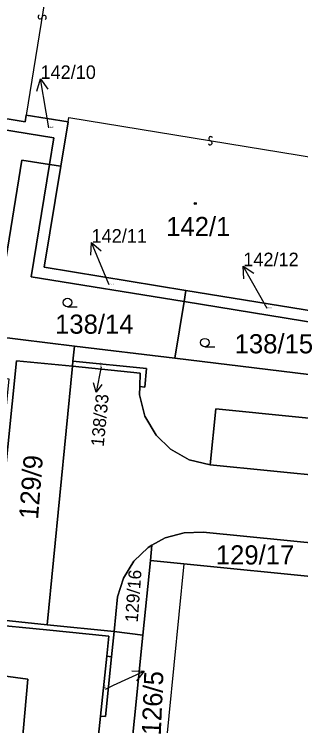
# Model space of a CAD drawing. Extents: x -598233 to -596890, y -1157848 to -1156431.
# Drawn here: x -597952.1 to -597926.7, y -1156881.8 to -1156818.7 of the extents above; entities that cross this region are included whole.
import ezdxf

# ---------------------------------------------------------------- set-up
doc = ezdxf.new("R2010")
doc.units = 0
for name, color, linetype in [('Level 1', 7, 'Continuous'), ('Level 13', 7, 'Continuous'), ('Level 3', 7, 'Continuous'), ('Level 4', 7, 'Continuous'), ('Level 5', 7, 'Continuous'), ('Level 57', 7, 'Continuous'), ('Level 60', 7, 'Continuous')]:
    doc.layers.add(name, color=color, linetype=linetype)

msp = doc.modelspace()

# ---------------------------------------------------------------- linework, layer by layer
at = {"layer": 'Level 1'}
for points in [[(-597951.07, -1156827.62), (-597951.16, -1156828.21), (-597960.5, -1156826.69)], [(-597947.37, -1156828.22), (-597951.07, -1156827.62)], [(-597960.66, -1156827.68), (-597948.63, -1156829.64), (-597949.01, -1156832.01)], [(-597948.02, -1156832.17), (-597947.37, -1156828.22)], [(-597949.01, -1156832.01), (-597951.45, -1156831.62), (-597954, -1156847.25)], [(-597949.01, -1156832.01), (-597950.63, -1156841.96), (-597937.08, -1156844.16)], [(-597949.01, -1156832.01), (-597948.02, -1156832.17)], [(-597948.02, -1156832.17), (-597949.48, -1156841.13), (-597936.92, -1156843.18)], [(-597922.25, -1156832.31), (-597924.36, -1156845.22), (-597936.92, -1156843.18)], [(-597937.08, -1156844.16), (-597923.53, -1156846.37), (-597921.43, -1156833.46), (-597918.2, -1156833.98)], [(-597937.9, -1156849.2), (-597920.2, -1156851.34), (-597918.2, -1156833.98)], [(-597937.08, -1156844.16), (-597936.92, -1156843.18)], [(-597937.08, -1156844.16), (-597937.9, -1156849.2)], [(-597946.8, -1156848.12), (-597954, -1156847.25)], [(-597946.8, -1156848.12), (-597946.93, -1156849.44)], [(-597937.9, -1156849.2), (-597946.8, -1156848.12)], [(-597946.98, -1156849.91), (-597951.92, -1156849.41), (-597954.27, -1156872.32), (-597949.22, -1156872.83)], [(-597946.98, -1156849.91), (-597946.93, -1156849.44)], [(-597946.93, -1156849.44), (-597940.41, -1156850.11), (-597940.57, -1156851.75), (-597941.01, -1156851.71)], [(-597949.22, -1156872.83), (-597946.98, -1156849.91)], [(-597941.01, -1156851.71), (-597940.97, -1156850.51), (-597946.98, -1156849.91)], [(-597941.01, -1156851.71), (-597941.03, -1156852.43), (-597940.55, -1156854.34), (-597939.55, -1156856.03), (-597938.3, -1156857.26), (-597936.63, -1156858.21), (-597934.76, -1156858.66)], [(-597897.36, -1156862.39), (-597896.91, -1156857.43), (-597934.27, -1156853.68), (-597934.76, -1156858.66)], [(-597934.76, -1156858.66), (-597897.36, -1156862.39)], [(-597939.93, -1156865.79), (-597938.76, -1156865.13), (-597937.07, -1156864.67), (-597935.39, -1156864.63), (-597924.39, -1156865.73)], [(-597939.93, -1156865.79), (-597940.28, -1156865.99), (-597941.54, -1156867.2), (-597942.46, -1156868.69), (-597942.98, -1156870.36), (-597943.29, -1156873.42)], [(-597939.93, -1156865.79), (-597940.07, -1156867.14)], [(-597940.73, -1156873.76), (-597940.07, -1156867.14)], [(-597940.07, -1156867.14), (-597937.1, -1156867.44)], [(-597937.1, -1156867.44), (-597924.66, -1156868.68)], [(-597954.69, -1156871.91), (-597954.77, -1156872.75), (-597949.27, -1156873.3), (-597943.75, -1156873.85), (-597943.94, -1156875.61)], [(-597984.59, -1156873.1), (-597950.92, -1156877.66), (-597952.15, -1156891.27), (-597949.01, -1156901.17)], [(-597949.22, -1156872.83), (-597943.29, -1156873.42)], [(-597943.52, -1156875.67), (-597943.29, -1156873.42)], [(-597943.29, -1156873.42), (-597940.73, -1156873.76)], [(-597901.17, -1156895.17), (-597900.87, -1156892.64), (-597942.21, -1156888.49), (-597940.73, -1156873.76)], [(-597943.94, -1156875.61), (-597944.5, -1156880.94)], [(-597943.94, -1156875.61), (-597943.52, -1156875.67)], [(-597943.52, -1156875.67), (-597944.05, -1156880.98), (-597944.5, -1156880.94)], [(-597944.5, -1156880.94), (-597945.65, -1156891.92), (-597949.01, -1156901.17)]]:
    msp.add_lwpolyline(points, dxfattribs=at)
at = {"layer": 'Level 13'}
for centre, start, end in [((-597949.842, -1156818.91), 117.96897, 350.55897), ((-597949.478, -1156818.971), 298.18343, 170.28142), ((-597934.719, -1156829.718), 28.12507, 260.22307), ((-597934.78, -1156830.082), 207.91061, 80.50061)]:
    msp.add_arc(centre, 0.184, start, end, dxfattribs=at)
at = {"layer": 'Level 3'}
for points in [[(-597948.26, -1156810.25), (-597951.07, -1156827.62)], [(-597947.37, -1156828.22), (-597947.31, -1156827.85), (-597922.19, -1156831.94), (-597922.25, -1156832.31)], [(-597937.1, -1156867.44), (-597938.88, -1156885.4), (-597914.65, -1156887.82), (-597912.89, -1156869.86)]]:
    msp.add_lwpolyline(points, dxfattribs=at)
at = {"layer": 'Level 5'}
for p, q in [((-597947.42, -1156844.63), (-597946.545, -1156844.63)), ((-597935.24, -1156848.18), (-597934.365, -1156848.18))]:
    msp.add_line(p, q, dxfattribs=at)
for centre, radius in [((-597936.09, -1156835.47), 0.09), ((-597936.09, -1156835.47), 0.0521), ((-597947.42, -1156844.255), 0.375), ((-597935.24, -1156847.805), 0.375)]:
    msp.add_circle(centre, radius, dxfattribs=at)
at = {"layer": 'Level 57'}
for p, q in [((-597949.312, -1156827.379), (-597949.809, -1156824.42)), ((-597949.08, -1156828.76), (-597949.312, -1156827.379)), ((-597944.124, -1156841.706), (-597945.285, -1156838.94)), ((-597930.365, -1156843.643), (-597931.838, -1156841.03)), ((-597943.72, -1156842.67), (-597944.124, -1156841.706)), ((-597929.73, -1156844.77), (-597930.365, -1156843.643)), ((-597944.44, -1156849.97), (-597944.878, -1156852.202)), ((-597943.328, -1156878.205), (-597940.607, -1156876.942)), ((-597944.05, -1156878.54), (-597943.328, -1156878.205))]:
    msp.add_line(p, q, dxfattribs=at)
for points in [[(-597950.136, -1156825.489), (-597949.809, -1156824.42), (-597949.15, -1156825.324)], [(-597945.359, -1156840.055), (-597945.285, -1156838.94), (-597944.437, -1156839.668)], [(-597931.783, -1156842.146), (-597931.838, -1156841.03), (-597930.912, -1156841.655)], [(-597944.36, -1156851.531), (-597944.878, -1156852.202), (-597945.104, -1156851.385)], [(-597941.724, -1156876.909), (-597940.607, -1156876.942), (-597941.303, -1156877.816)]]:
    msp.add_lwpolyline(points, dxfattribs=at)
at = {"layer": 'Level 60'}
for points in [[(-597924.36, -1156845.22), (-597936.92, -1156843.18), (-597949.48, -1156841.13), (-597948.02, -1156832.17), (-597947.37, -1156828.22), (-597951.07, -1156827.62), (-597951.16, -1156828.21), (-597960.5, -1156826.69), (-597963.66, -1156826.17), (-597966.13, -1156825.77), (-597968.6, -1156825.37), (-597971.06, -1156824.97), (-597973.53, -1156824.56), (-597976.31, -1156824.11), (-597973.36, -1156805.99), (-597948.23, -1156810.07), (-597948.26, -1156810.25), (-597944.72, -1156810.83), (-597944.52, -1156810.86), (-597919.65, -1156814.92)], [(-597896.91, -1156857.43), (-597934.27, -1156853.68), (-597934.76, -1156858.66), (-597936.63, -1156858.21), (-597938.3, -1156857.26), (-597939.55, -1156856.03), (-597940.55, -1156854.34), (-597941.03, -1156852.43), (-597941.01, -1156851.71), (-597940.57, -1156851.75), (-597940.41, -1156850.11), (-597946.93, -1156849.44), (-597946.8, -1156848.12), (-597937.9, -1156849.2), (-597920.2, -1156851.34)], [(-597924.39, -1156865.73), (-597935.39, -1156864.63), (-597937.07, -1156864.67), (-597938.76, -1156865.13), (-597939.93, -1156865.79), (-597940.28, -1156865.99), (-597941.54, -1156867.2), (-597942.46, -1156868.69), (-597942.98, -1156870.36), (-597943.29, -1156873.42), (-597949.22, -1156872.83), (-597946.98, -1156849.91), (-597940.97, -1156850.51), (-597941.01, -1156851.71), (-597941.03, -1156852.43), (-597940.55, -1156854.34), (-597939.55, -1156856.03), (-597938.3, -1156857.26), (-597936.63, -1156858.21), (-597934.76, -1156858.66), (-597897.36, -1156862.39)], [(-597987.21, -1156882.02), (-597984.59, -1156873.1), (-597950.92, -1156877.66), (-597952.15, -1156891.27)]]:
    msp.add_lwpolyline(points, dxfattribs=at)
for points in [[(-597951.16, -1156828.21), (-597951.07, -1156827.62), (-597947.37, -1156828.22), (-597948.02, -1156832.17), (-597949.01, -1156832.01), (-597948.63, -1156829.64), (-597960.66, -1156827.68), (-597960.5, -1156826.69)], [(-597964.06, -1156846.03), (-597972.44, -1156844.73), (-597983.58, -1156843.11), (-597983.64, -1156835.62), (-597988.74, -1156835.65), (-597988.71, -1156833.81), (-597962.3, -1156838), (-597961.29, -1156831.63), (-597960.66, -1156827.68), (-597948.63, -1156829.64), (-597949.01, -1156832.01), (-597951.45, -1156831.62), (-597954, -1156847.25)], [(-597951.45, -1156831.62), (-597949.01, -1156832.01), (-597950.63, -1156841.96), (-597937.08, -1156844.16), (-597937.9, -1156849.2), (-597946.8, -1156848.12), (-597954, -1156847.25)], [(-597948.02, -1156832.17), (-597949.48, -1156841.13), (-597936.92, -1156843.18), (-597937.08, -1156844.16), (-597950.63, -1156841.96), (-597949.01, -1156832.01)], [(-597922.25, -1156832.31), (-597918.56, -1156832.91), (-597918.09, -1156832.99), (-597918.2, -1156833.98), (-597921.43, -1156833.46), (-597923.53, -1156846.37), (-597937.08, -1156844.16), (-597936.92, -1156843.18), (-597924.36, -1156845.22)], [(-597937.9, -1156849.2), (-597937.08, -1156844.16), (-597923.53, -1156846.37), (-597921.43, -1156833.46), (-597918.2, -1156833.98), (-597920.2, -1156851.34)], [(-597964.6, -1156849.19), (-597964.06, -1156846.03), (-597954, -1156847.25), (-597946.8, -1156848.12), (-597946.93, -1156849.44), (-597946.98, -1156849.91), (-597951.92, -1156849.41), (-597954.27, -1156872.32), (-597949.22, -1156872.83), (-597943.29, -1156873.42), (-597943.52, -1156875.67), (-597943.94, -1156875.61), (-597943.75, -1156873.85), (-597949.27, -1156873.3), (-597954.77, -1156872.75), (-597954.69, -1156871.91), (-597952.91, -1156854.27), (-597952.59, -1156851.06), (-597960.52, -1156850.34), (-597960.44, -1156849.76)], [(-597951.92, -1156849.41), (-597946.98, -1156849.91), (-597949.22, -1156872.83), (-597954.27, -1156872.32)], [(-597946.93, -1156849.44), (-597940.41, -1156850.11), (-597940.57, -1156851.75), (-597941.01, -1156851.71), (-597940.97, -1156850.51), (-597946.98, -1156849.91)], [(-597897.36, -1156862.39), (-597934.76, -1156858.66), (-597934.27, -1156853.68), (-597896.91, -1156857.43)], [(-597939.93, -1156865.79), (-597938.76, -1156865.13), (-597937.07, -1156864.67), (-597935.39, -1156864.63), (-597924.39, -1156865.73), (-597924.66, -1156868.68), (-597937.1, -1156867.44), (-597940.07, -1156867.14)], [(-597940.73, -1156873.76), (-597943.29, -1156873.42), (-597942.98, -1156870.36), (-597942.46, -1156868.69), (-597941.54, -1156867.2), (-597940.28, -1156865.99), (-597939.93, -1156865.79), (-597940.07, -1156867.14)], [(-597924.66, -1156868.68), (-597912.89, -1156869.86), (-597870.08, -1156874.13), (-597853.45, -1156875.79), (-597845.88, -1156876.55), (-597847.67, -1156894.51), (-597847.98, -1156897.84), (-597872.79, -1156895.42), (-597878.73, -1156894.84), (-597896.71, -1156893.08), (-597896.99, -1156895.59), (-597888.88, -1156896.39), (-597888.91, -1156896.69), (-597890.67, -1156914.32), (-597914.9, -1156911.93), (-597913.45, -1156897.52), (-597913.09, -1156893.99), (-597901.17, -1156895.17), (-597900.87, -1156892.64), (-597942.21, -1156888.49), (-597940.73, -1156873.76), (-597940.07, -1156867.14), (-597937.1, -1156867.44)], [(-597950.92, -1156877.66), (-597984.59, -1156873.1), (-597983.76, -1156870.27), (-597983.13, -1156868.14), (-597980.45, -1156868.5), (-597954.69, -1156871.91), (-597954.77, -1156872.75), (-597949.27, -1156873.3), (-597943.75, -1156873.85), (-597943.94, -1156875.61), (-597944.5, -1156880.94), (-597945.65, -1156891.92), (-597949.01, -1156901.17), (-597952.15, -1156891.27)], [(-597913.09, -1156893.99), (-597913.45, -1156897.52), (-597923.4, -1156896.53), (-597925.52, -1156917.66), (-597950.3, -1156915.42), (-597949.77, -1156909.6), (-597949.34, -1156904.8), (-597949.01, -1156901.17), (-597945.65, -1156891.92), (-597944.5, -1156880.94), (-597944.05, -1156880.98), (-597943.52, -1156875.67), (-597943.29, -1156873.42), (-597940.73, -1156873.76), (-597942.21, -1156888.49), (-597900.87, -1156892.64), (-597901.17, -1156895.17)], [(-597944.5, -1156880.94), (-597943.94, -1156875.61), (-597943.52, -1156875.67), (-597944.05, -1156880.98)]]:
    msp.add_lwpolyline(points, close=True, dxfattribs=at)

# ---------------------------------------------------------------- texts
at = {"layer": 'Level 4'}
for s, height, p in [('142/10', 0.1, (-597949.08, -1156828.76)), ('142/1', 1.7, (-597938.67, -1156838.36)), ('142/11', 0.1, (-597943.72, -1156842.67)), ('142/12', 0.1, (-597929.73, -1156844.77)), ('138/14', 1.7, (-597948.514, -1156847.02)), ('138/15', 1.7, (-597932.605, -1156848.76)), ('129/17', 1.7, (-597934.273, -1156867.49))]:
    msp.add_text(s, height=height, dxfattribs=at).set_placement(p)
for s, height, rotation, p in [('138/33', 0.1, 84.41811, (-597944.44, -1156849.97)), ('129/9', 1.7, 85.5, (-597950.029, -1156863.529)), ('129/16', 1.14, 85.70556, (-597941.194, -1156872.653)), ('126/5', 0.1, 87.54849, (-597944.05, -1156878.54))]:
    msp.add_text(s, height=height, rotation=rotation, dxfattribs=at).set_placement(p)
at = {"layer": 'Level 57'}
for s, p in [('142/10', (-597949.809, -1156824.42)), ('142/11', (-597945.285, -1156838.94)), ('142/12', (-597931.838, -1156841.03))]:
    msp.add_text(s, height=1.2, dxfattribs=at).set_placement(p)
for s, height, rotation, p in [('138/33', 1.14, 84.41811, (-597944.208, -1156857.069)), ('126/5', 1.7, 87.54849, (-597939.151, -1156882.666))]:
    msp.add_text(s, height=height, rotation=rotation, dxfattribs=at).set_placement(p)

doc.saveas('drawing.dxf')
